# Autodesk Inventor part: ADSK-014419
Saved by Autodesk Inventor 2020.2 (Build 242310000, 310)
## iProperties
_SkeletonDoc: Frame Skeleton File
_Version: 15.0.0
Part Number: ADSK-014419
Material: Allgemein
Description: Framegenerator-Skeleton-Referenz
Document SubType Name: Modellieren
Designer: lutzd
Density: 1 g/cm^3
Appearance: Vorgabe
DocNumber: ADSK-014419
Folder: .
Mass: 0 kg
VLT_Material: Generisch
Dimensions: 0x0x0 mm
Title: Gestellrahmenbauteil(e)
Author: lutzd
Revision Number: -
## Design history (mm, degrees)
sketch "Referenzrahmen"
node "Volumenkörper"
node "Flächenkörper"
